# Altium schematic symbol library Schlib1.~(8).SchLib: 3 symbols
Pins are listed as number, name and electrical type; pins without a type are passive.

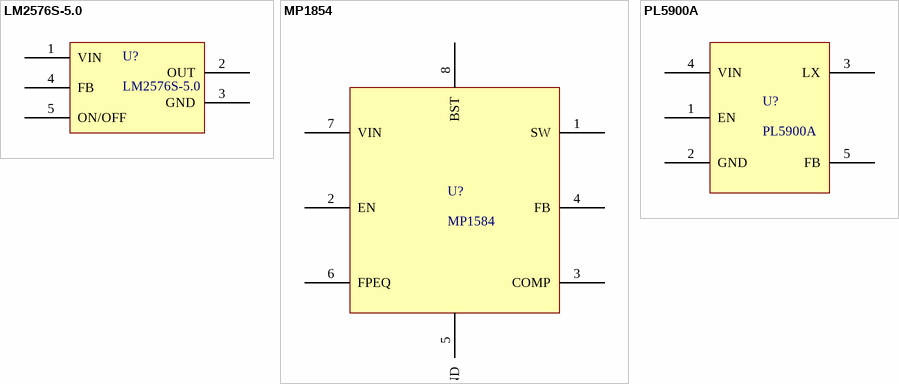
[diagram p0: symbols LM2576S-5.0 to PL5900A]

## LM2576S-5.0
designator U?
footprint TO263-5A (263，5脚晶体管)
pins: 1 VIN, 2 OUT, 3 GND, 4 FB, 5 ON/OFF

## MP1854
designator U?, comment MP1584
footprint SOP8_L (5*6*1.8mm（长宽高）)
pins: 1 SW, 2 EN, 3 COMP, 4 FB, 5 GND, 6 FPEQ, 7 VIN, 8 BST

## PL5900A
designator U?
footprint SOT23-5L (3x1.6x1.1mm(长宽高))
pins: 1 EN, 2 GND, 3 LX, 4 VIN, 5 FB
